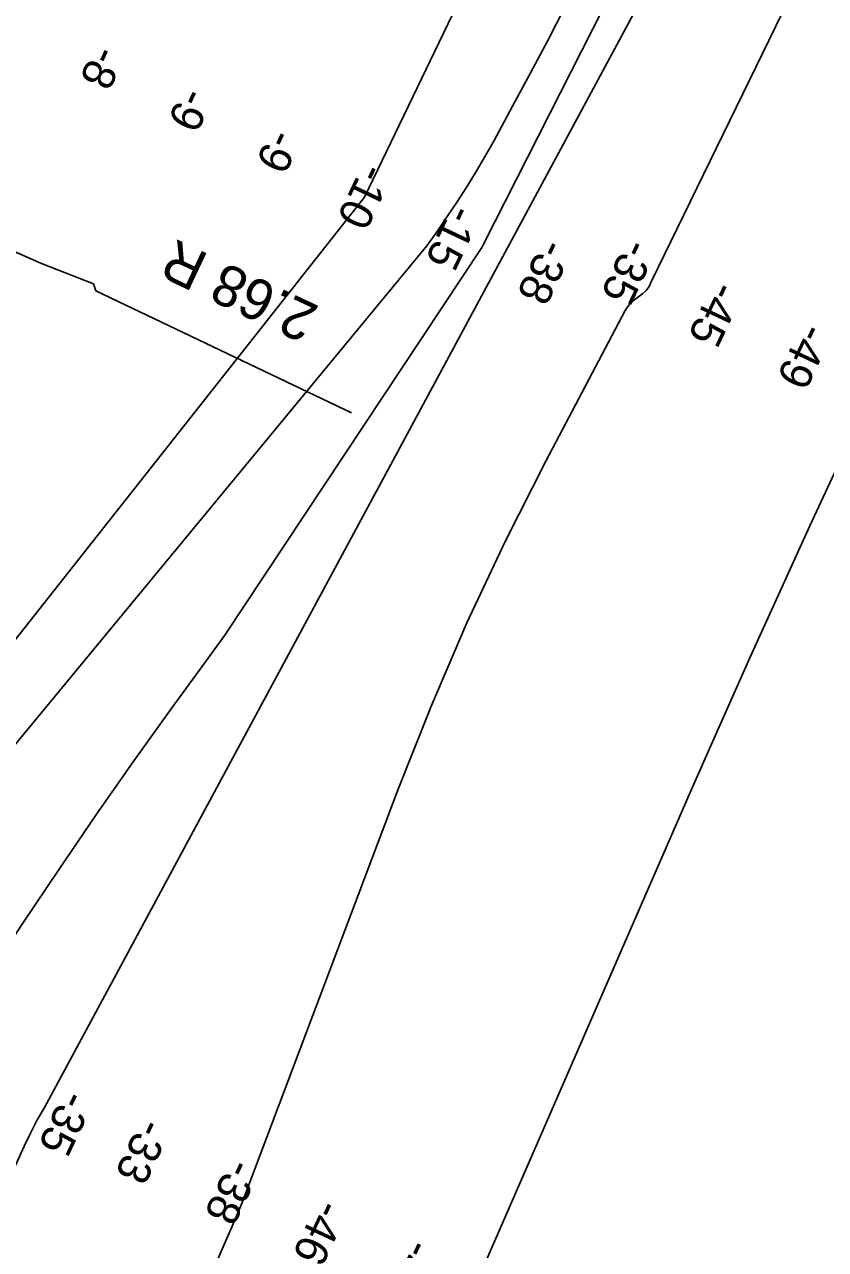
# Model space of a CAD drawing. Extents: x 3930721 to 3950824, y 220441 to 242861.
# Drawn here: x 3939489 to 3940311, y 228722 to 229978 of the extents above; entities that cross this region are included whole.
import ezdxf

# ---------------------------------------------------------------- set-up
doc = ezdxf.new("R2010")
doc.units = 0
for name, color, linetype in [('V-LEVE-TOET', 7, 'Continuous'), ('V-RIVR-RANG', 7, 'Continuous'), ('V-STRM-FMON', 7, 'Continuous'), ('V-TOPO-DPTH', 7, 'Continuous'), ('V-TOPO-MAJR', 7, 'Continuous'), ('V-TOPO-MINR', 7, 'Continuous')]:
    doc.layers.add(name, color=color, linetype=linetype)

msp = doc.modelspace()

# ---------------------------------------------------------------- linework, layer by layer
at = {"layer": 'V-LEVE-TOET'}
msp.add_lwpolyline([(3939445.1, 229760.4), (3939506.6, 229733.1), (3939560.1, 229712.5), (3939562.6, 229705.2), (3939824.8, 229580.1)], dxfattribs=at)
at = {"layer": 'V-TOPO-DPTH'}
for points in [[(3939138.4, 228899.8), (3939165.6, 228949.6), (3939838.2, 229801.2), (3940275.6, 230709.6), (3940672.4, 231617.7), (3940572, 231858.6), (3940567.3, 231867.1), (3940561.5, 231871.8), (3940554.1, 231870.8), (3940545.6, 231866.1), (3940533.6, 231848.4), (3940521.9, 231830.6), (3940510.6, 231812.5), (3940499.5, 231794.3), (3940486, 231771.5), (3940470.4, 231745.8), (3940454.4, 231720.3), (3940437.9, 231695.2), (3940421, 231670.3), (3940394.3, 231631.9), (3940546.9, 231888.2), (3940838.9, 231677.1)], [(3940951.1, 231818.3), (3940831.5, 231527.8), (3940778.6, 231417.8), (3940749.9, 231356.3), (3940722.3, 231294.3), (3940696.2, 231231.7), (3940671.1, 231168.7), (3940471.6, 230649.8), (3940468.6, 230644.6), (3940464.8, 230640.4), (3939509.5, 228866.7), (3939502.1, 228854.1), (3939495.4, 228841.1), (3939489.1, 228827.8), (3939432.4, 228702.8), (3939397.6, 228627.1), (3939362.1, 228551.7), (3939325.7, 228476.7), (3939288.7, 228402.1), (3939055.8, 227939.6)], [(3940951.1, 231818.3), (3940831.5, 231527.8), (3940778.6, 231417.8), (3940749.9, 231356.3), (3940722.3, 231294.3), (3940696.2, 231231.7), (3940671.1, 231168.7), (3940471.6, 230649.8), (3940468.6, 230644.6), (3940464.8, 230640.4), (3939509.5, 228866.7), (3939502.1, 228854.1), (3939495.4, 228841.1), (3939489.1, 228827.8), (3939432.4, 228702.8), (3939397.6, 228627.1), (3939362.1, 228551.7), (3939325.7, 228476.7), (3939288.7, 228402.1), (3939055.8, 227939.6)], [(3939325.9, 227881.3), (3939705.8, 228753.5), (3939708.6, 228760), (3939711.3, 228766.6), (3939714, 228773.2), (3939716.5, 228779.9), (3939872.6, 229193.9), (3939906.8, 229279.7), (3939943.1, 229364.6), (3939982.6, 229448.1), (3940024.2, 229530.6), (3940105.7, 229684.9), (3940108.5, 229689.2), (3940111.7, 229693.1), (3940115.4, 229696.4), (3940119.7, 229699.3), (3940123.7, 229702.3), (3940127.3, 229705.7), (3940130.1, 229709.8), (3940132.3, 229714.4), (3940568.4, 230608.9)], [(3940568.4, 230608.9), (3940132.3, 229714.4), (3940130.1, 229709.8), (3940127.3, 229705.7), (3940123.7, 229702.3), (3940119.7, 229699.3), (3940115.4, 229696.4), (3940111.7, 229693.1), (3940108.5, 229689.2), (3940105.7, 229684.9), (3940024.2, 229530.6), (3939982.6, 229448.1), (3939943.1, 229364.6), (3939906.8, 229279.7), (3939872.6, 229193.9), (3939716.5, 228779.9), (3939714, 228773.2), (3939711.3, 228766.6), (3939708.6, 228760), (3939705.8, 228753.5), (3939325.9, 227881.3)], [(3940325.4, 230476.1), (3940297.3, 230418.7), (3940268.9, 230361.5), (3940240.2, 230304.5), (3939960.7, 229753.9), (3939958.5, 229749.8), (3939695, 229351.9), (3939671.1, 229319.5), (3939639.8, 229276.4), (3939600.9, 229222), (3939562.5, 229167.2), (3939524.8, 229111.9), (3939487.6, 229056.3), (3939415.1, 228946.4), (3939402.2, 228926.8), (3939389.1, 228907.3), (3939375.9, 228887.8), (3939362.7, 228868.4), (3939290.3, 228763), (3939263, 228724.4)], [(3939263, 228724.4), (3939290.3, 228763), (3939362.7, 228868.4), (3939375.9, 228887.8), (3939389.1, 228907.3), (3939402.2, 228926.8), (3939415.1, 228946.4), (3939487.6, 229056.3), (3939524.8, 229111.9), (3939562.5, 229167.2), (3939600.9, 229222), (3939639.8, 229276.4), (3939671.1, 229319.5), (3939695, 229351.9), (3939958.5, 229749.8), (3939960.7, 229753.9), (3940240.2, 230304.5), (3940268.9, 230361.5), (3940297.3, 230418.7), (3940325.4, 230476.1)]]:
    msp.add_lwpolyline(points, dxfattribs=at)
at = {"layer": 'V-TOPO-MAJR'}
msp.add_lwpolyline([(3940324.8, 229528), (3940295.2, 229464), (3940264.2, 229396.4), (3940233.5, 229328.7), (3940203.3, 229260.8), (3940173.4, 229192.8), (3939956.5, 228695.5), (3939950, 228680.3), (3939943.7, 228665.1), (3939937.6, 228649.7), (3939931.7, 228634.2), (3939902.1, 228555.4), (3939881.9, 228500.3), (3939862.2, 228445.1), (3939843.3, 228389.7), (3939824.8, 228334), (3939812.5, 228296.1), (3939794, 228238.7), (3939775.8, 228181.2), (3939757.9, 228123.6), (3939740.2, 228065.9), (3939722.1, 228008.4)], dxfattribs=at)
at = {"layer": 'V-TOPO-MINR'}
for points in [[(3940394.3, 231631.9), (3940421, 231670.3), (3940437.9, 231695.2), (3940454.4, 231720.3), (3940470.4, 231745.8), (3940486, 231771.5), (3940499.5, 231794.3), (3940510.6, 231812.5), (3940521.9, 231830.6), (3940533.6, 231848.4), (3940545.6, 231866.1), (3940554.1, 231870.8), (3940561.5, 231871.8), (3940567.3, 231867.1), (3940572, 231858.6), (3940672.4, 231617.7), (3940275.6, 230709.6), (3939838.2, 229801.2), (3939165.6, 228949.6), (3939138.4, 228899.8)], [(3940951.1, 231818.3), (3940831.5, 231527.8), (3940778.6, 231417.8), (3940749.9, 231356.3), (3940722.3, 231294.3), (3940696.2, 231231.7), (3940671.1, 231168.7), (3940471.6, 230649.8), (3940468.6, 230644.6), (3940464.8, 230640.4), (3939509.5, 228866.7), (3939502.1, 228854.1), (3939495.4, 228841.1), (3939489.1, 228827.8), (3939432.4, 228702.8), (3939397.6, 228627.1), (3939362.1, 228551.7), (3939325.7, 228476.7), (3939288.7, 228402.1), (3939055.8, 227939.6)], [(3940568.4, 230608.9), (3940132.3, 229714.4), (3940130.1, 229709.8), (3940127.3, 229705.7), (3940123.7, 229702.3), (3940119.7, 229699.3), (3940115.4, 229696.4), (3940111.7, 229693.1), (3940108.5, 229689.2), (3940105.7, 229684.9), (3940024.2, 229530.6), (3939982.6, 229448.1), (3939943.1, 229364.6), (3939906.8, 229279.7), (3939872.6, 229193.9), (3939716.5, 228779.9), (3939714, 228773.2), (3939711.3, 228766.6), (3939708.6, 228760), (3939705.8, 228753.5), (3939325.9, 227881.3)], [(3940321, 230537.5), (3940061.5, 230030.2), (3940043.9, 229996.1), (3940026.2, 229962.1), (3940008.2, 229928.3), (3939990.1, 229894.5), (3939971.1, 229859.3), (3939962.1, 229843.3), (3939952.9, 229827.5), (3939943.2, 229811.9), (3939933.2, 229796.5), (3939923, 229781.4), (3939912.6, 229766.2), (3939902.1, 229751.2), (3939256.2, 228969.7), (3939182.6, 228836.6)], [(3940325.4, 230476.1), (3940297.3, 230418.7), (3940268.9, 230361.5), (3940240.2, 230304.5), (3939960.7, 229753.9), (3939958.5, 229749.8), (3939695, 229351.9), (3939671.1, 229319.5), (3939639.8, 229276.4), (3939600.9, 229222), (3939562.5, 229167.2), (3939524.8, 229111.9), (3939487.6, 229056.3), (3939415.1, 228946.4), (3939402.2, 228926.8), (3939389.1, 228907.3), (3939375.9, 228887.8), (3939362.7, 228868.4), (3939290.3, 228763), (3939263, 228724.4)]]:
    msp.add_lwpolyline(points, dxfattribs=at)

# ---------------------------------------------------------------- texts
at = {"layer": 'V-RIVR-RANG'}
for s, rotation, p in [('-8', 244.6383, (3939562.4, 229958.8)), ('-9', 244.6383, (3939652.7, 229915.8)), ('-9', 244.6383, (3939743.1, 229873.2)), ('-10', 244.6383, (3939837.1, 229838)), ('-15', 244.6383, (3939927.7, 229795.7)), ('-38', 244.6383, (3940021.7, 229760.5)), ('-35', 244.7791, (3940107.7, 229760.5)), ('-45', 244.7791, (3940197.1, 229717.1)), ('-49', 244.7791, (3940288.1, 229674.1)), ('-35', 244.6983, (3939530.5, 228887.1)), ('-33', 244.8402, (3939609.3, 228858.2)), ('-38', 244.8402, (3939700.8, 228816.7)), ('-46', 244.8402, (3939791.4, 228774.9)), ('-49', 244.8402, (3939883.5, 228734.4))]:
    msp.add_text(s, height=33.5, rotation=rotation, dxfattribs=at).set_placement(p)
at = {"layer": 'V-STRM-FMON'}
msp.add_text('2.68 R', height=42, rotation=154.8054, dxfattribs=at).set_placement((3939793.1, 229688.7))

doc.saveas('drawing.dxf')
